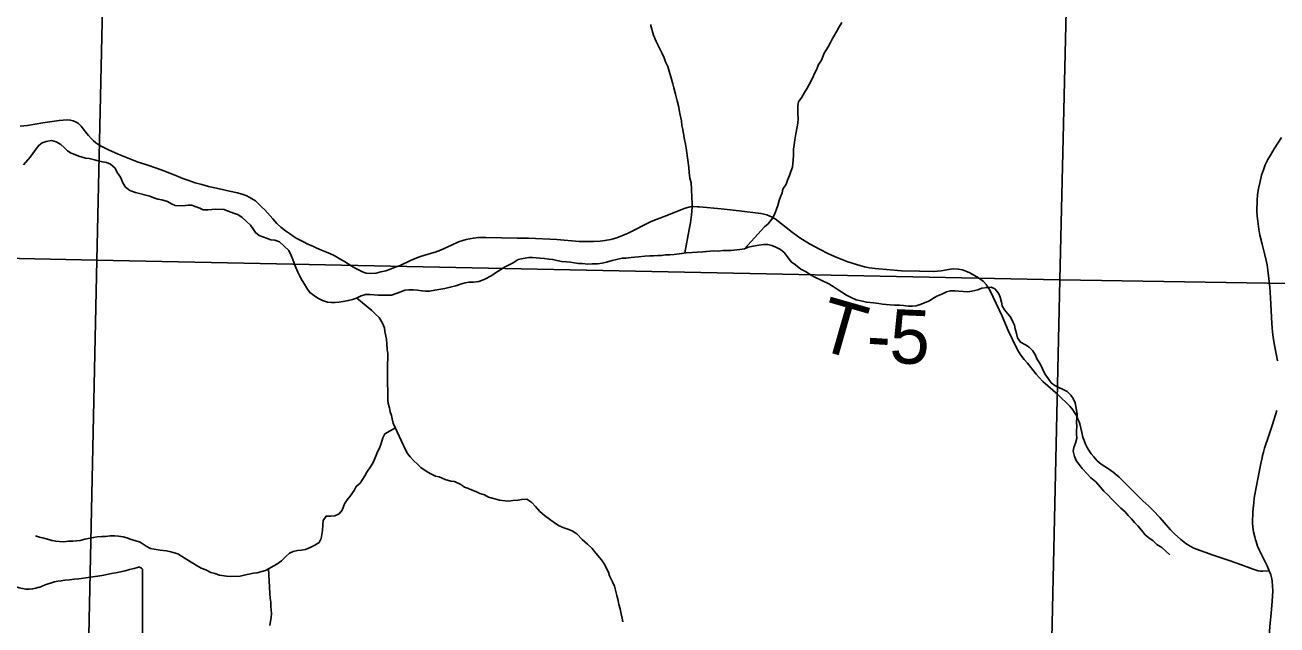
# Model space of a CAD drawing. Extents: x 0 to 34, y 0 to 22.
# Drawn here: x 27.832 to 29.148, y 19.195 to 19.826 of the extents above; entities that cross this region are included whole.
import ezdxf

# ---------------------------------------------------------------- set-up
doc = ezdxf.new("R2010")
doc.units = 0
for name, color, linetype in [('GM_X_Corporation', 7, 'Continuous'), ('GM_X_County_Road', 7, 'Continuous'), ('GM_X_Minor_River', 7, 'Continuous'), ('GM_X_State_Shield', 7, 'Continuous'), ('GM_X_Township_Road', 7, 'Continuous'), ('GM_X_Township_Road_Text', 7, 'Continuous')]:
    doc.layers.add(name, color=color, linetype=linetype)

msp = doc.modelspace()

# ---------------------------------------------------------------- linework, layer by layer
at = {"layer": 'GM_X_Corporation'}
for points in [[(28.9396, 20.3907), (28.9198, 19.5578), (27.9077, 19.5783), (27.9263, 20.4078)], [(29.9657, 20.3723), (29.946, 19.5413), (28.9198, 19.5578), (28.9396, 20.3907)], [(27.9077, 19.5783), (27.8861, 18.5601), (27.0567, 18.5863), (27.0782, 19.5962)], [(27.9077, 19.5783), (28.9198, 19.5578), (28.8973, 18.5532), (27.8861, 18.5601)], [(28.9198, 19.5578), (29.946, 19.5413), (29.9261, 18.5329), (28.8973, 18.5532)]]:
    msp.add_lwpolyline(points, close=True, dxfattribs=at)
at = {"layer": 'GM_X_County_Road'}
for points in [[(29.1486, 19.4725), (29.1455, 19.4893), (29.1441, 19.4973), (29.1434, 19.5031), (29.1429, 19.5074), (29.1425, 19.512), (29.1411, 19.5387), (29.1404, 19.55), (29.1395, 19.5593), (29.1384, 19.5681), (29.1376, 19.5737), (29.1367, 19.5781), (29.1354, 19.5839), (29.1325, 19.5952), (29.13, 19.6046), (29.1288, 19.6112), (29.1278, 19.6194), (29.1273, 19.6247), (29.127, 19.6298), (29.1271, 19.6414), (29.1277, 19.647), (29.1286, 19.6537), (29.1302, 19.6611), (29.1319, 19.6679), (29.1338, 19.6735), (29.1357, 19.6785), (29.1384, 19.6842), (29.1411, 19.6889), (29.1451, 19.6954), (29.1529, 19.7074)], [(29.1391, 19.1751), (29.1408, 19.1975), (29.1418, 19.2073), (29.143, 19.2202), (29.1437, 19.2305), (29.1435, 19.2363), (29.143, 19.2412), (29.1427, 19.2435), (29.1415, 19.2478), (29.1399, 19.2519), (29.1376, 19.2572), (29.136, 19.2606), (29.1297, 19.2733), (29.1277, 19.2779), (29.126, 19.2828), (29.1256, 19.2845), (29.1247, 19.2876), (29.1235, 19.2928), (29.1228, 19.2979), (29.1224, 19.3024), (29.1226, 19.3137), (29.1229, 19.3174), (29.1236, 19.3235), (29.1242, 19.3283), (29.1259, 19.3377), (29.131, 19.3649), (29.1323, 19.3709), (29.1328, 19.3732), (29.1337, 19.3767), (29.1349, 19.381), (29.1397, 19.3953), (29.1433, 19.4059), (29.148, 19.4205)]]:
    msp.add_lwpolyline(points, dxfattribs=at)
at = {"layer": 'GM_X_Minor_River'}
for points in [[(28.6909, 19.8282), (28.688, 19.8236), (28.6854, 19.819), (28.681, 19.8113), (28.6788, 19.8071), (28.6763, 19.8025), (28.6722, 19.796), (28.6693, 19.7887), (28.666, 19.7834), (28.6646, 19.7792), (28.662, 19.7746), (28.6602, 19.7703), (28.6565, 19.7631), (28.6543, 19.7592), (28.6514, 19.7546), (28.6488, 19.7497), (28.6451, 19.745), (28.6444, 19.7409), (28.6446, 19.7318), (28.6447, 19.7272), (28.6444, 19.7223), (28.6437, 19.7185), (28.6423, 19.7112), (28.6413, 19.7048), (28.6406, 19.6998), (28.6399, 19.6952), (28.6401, 19.688), (28.6394, 19.6801), (28.6388, 19.6763), (28.6373, 19.6717), (28.6359, 19.6675), (28.6337, 19.6625), (28.6323, 19.6583), (28.6289, 19.6529), (28.6279, 19.6491), (28.6264, 19.6449), (28.625, 19.6411), (28.6236, 19.6358), (28.6221, 19.6319), (28.62, 19.6266), (28.617, 19.6216), (28.6133, 19.6166), (28.6096, 19.6135), (28.5884, 19.5904)], [(28.4897, 19.8261), (28.4929, 19.8148), (28.4957, 19.8084), (28.4972, 19.8047), (28.5019, 19.7956), (28.5039, 19.7911), (28.5055, 19.787), (28.5078, 19.7821), (28.5091, 19.7772), (28.5111, 19.7711), (28.5131, 19.7636), (28.5143, 19.7594), (28.5159, 19.753), (28.5176, 19.7458), (28.5192, 19.7405), (28.5205, 19.7326), (28.5221, 19.7247), (28.5226, 19.7201), (28.5238, 19.7156), (28.5247, 19.7091), (28.5255, 19.7054), (28.5263, 19.7004), (28.5271, 19.6963), (28.5289, 19.6834), (28.5298, 19.6758), (28.5303, 19.6705), (28.5311, 19.6645), (28.5323, 19.6596), (28.5328, 19.6531), (28.533, 19.644), (28.5335, 19.6387), (28.5335, 19.6346), (28.5332, 19.63), (28.5329, 19.6262), (28.5316, 19.6178), (28.5302, 19.6106), (28.5258, 19.586)], [(27.8308, 19.6787), (27.8379, 19.6868), (27.8404, 19.6906), (27.8441, 19.6953), (27.8467, 19.6991), (27.8505, 19.7018), (27.8546, 19.703), (27.8603, 19.7043), (27.8652, 19.7028), (27.8698, 19.6999), (27.8736, 19.6969), (27.8771, 19.6932), (27.8809, 19.691), (27.8847, 19.6895), (27.8889, 19.6877), (27.8958, 19.6855), (27.8999, 19.6852), (27.9053, 19.6838), (27.9091, 19.6827), (27.9136, 19.6817), (27.9178, 19.681), (27.922, 19.6792), (27.927, 19.6751), (27.9293, 19.6706), (27.9325, 19.6657), (27.9356, 19.6589), (27.9379, 19.6552), (27.9425, 19.6515), (27.9486, 19.6497), (27.9635, 19.6458), (27.9677, 19.6439), (27.9718, 19.6425), (27.976, 19.6418), (27.9821, 19.64), (27.9863, 19.6378), (27.9901, 19.636), (27.9981, 19.6354), (28.0037, 19.6362), (28.0075, 19.6363), (28.0113, 19.6348), (28.0159, 19.633), (28.0197, 19.6312), (28.0243, 19.6313), (28.0329, 19.6322), (28.0417, 19.6316), (28.0474, 19.6294), (28.0523, 19.6276), (28.0561, 19.6265), (28.0607, 19.6232), (28.0646, 19.6195)], [(28.0646, 19.6195), (28.0692, 19.6154), (28.0719, 19.6116), (28.0746, 19.6075), (28.0785, 19.6045), (28.0861, 19.6016), (28.0907, 19.5998), (28.0948, 19.5995), (28.0998, 19.5977), (28.1048, 19.5932), (28.1094, 19.5887), (28.1121, 19.5835), (28.1137, 19.579), (28.1153, 19.5752), (28.1169, 19.5707), (28.1189, 19.5658), (28.1212, 19.5616), (28.1236, 19.5571), (28.1259, 19.5534), (28.1286, 19.5492), (28.1318, 19.5444), (28.1364, 19.541), (28.1402, 19.5384), (28.1451, 19.5359), (28.1501, 19.5344), (28.1539, 19.5338), (28.1584, 19.5338), (28.1622, 19.5343), (28.1667, 19.5351), (28.172, 19.536), (28.1765, 19.5372), (28.1807, 19.5384), (28.1855, 19.5411), (28.1901, 19.5424), (28.1946, 19.5424), (28.2033, 19.5418), (28.2086, 19.5415), (28.2173, 19.5417), (28.2222, 19.5433), (28.2271, 19.5453), (28.2316, 19.5469), (28.2358, 19.5473), (28.2403, 19.5474), (28.2448, 19.5471), (28.2494, 19.5464), (28.2532, 19.5457), (28.2574, 19.5458), (28.263, 19.5471), (28.2672, 19.5475), (28.2736, 19.5488), (28.2792, 19.55), (28.2849, 19.5516), (28.2901, 19.5532), (28.295, 19.5545), (28.2988, 19.5553), (28.3037, 19.5554), (28.3094, 19.5562), (28.3147, 19.5582), (28.3229, 19.5625), (28.3278, 19.5657), (28.3319, 19.5684), (28.3356, 19.5707), (28.3398, 19.5727), (28.3454, 19.5758), (28.3506, 19.579), (28.3559, 19.5802), (28.3619, 19.5814), (28.3657, 19.5811), (28.3733, 19.5805), (28.3782, 19.5802), (28.3828, 19.5795), (28.3869, 19.5792), (28.3911, 19.5782), (28.3961, 19.5771), (28.4014, 19.5768), (28.4055, 19.5765), (28.4093, 19.5758), (28.4143, 19.5748), (28.418, 19.5748), (28.4237, 19.5742), (28.4283, 19.5746), (28.4339, 19.5747), (28.4388, 19.5752), (28.4434, 19.5764), (28.4494, 19.5781), (28.4599, 19.5805), (28.4637, 19.5806), (28.4694, 19.5811), (28.4769, 19.582), (28.4838, 19.5825), (28.489, 19.5829), (28.4928, 19.583), (28.4974, 19.5835), (28.5011, 19.5835), (28.5053, 19.584), (28.5098, 19.5841), (28.5147, 19.5845), (28.5223, 19.5854), (28.5272, 19.5863), (28.5336, 19.5864), (28.5446, 19.5873)], [(28.5446, 19.5873), (28.5563, 19.5883), (28.5612, 19.588), (28.5658, 19.5885), (28.5741, 19.5886), (28.5835, 19.5895), (28.5884, 19.5904), (28.5922, 19.592), (28.5975, 19.5932), (28.6035, 19.5941), (28.6084, 19.5949), (28.6129, 19.595), (28.6171, 19.5939), (28.6213, 19.5921), (28.6263, 19.5895), (28.6301, 19.5866), (28.6336, 19.5821), (28.6375, 19.5768), (28.6421, 19.5735), (28.6475, 19.569), (28.6524, 19.5665), (28.6585, 19.5628), (28.6624, 19.5606), (28.6769, 19.5536), (28.6815, 19.5507), (28.686, 19.5481), (28.6906, 19.5448), (28.6956, 19.5418), (28.7006, 19.5392), (28.7059, 19.5367), (28.7124, 19.5353), (28.7166, 19.5342), (28.7241, 19.5336), (28.7295, 19.5329), (28.7336, 19.5322), (28.7374, 19.5319), (28.7416, 19.5316), (28.7461, 19.5313), (28.7514, 19.531), (28.7556, 19.5307), (28.7605, 19.5301), (28.7651, 19.5301), (28.7689, 19.5306), (28.7741, 19.5322), (28.7783, 19.5338), (28.7828, 19.5358), (28.7865, 19.5381), (28.7906, 19.5405), (28.7959, 19.5428), (28.8008, 19.5452), (28.8049, 19.5464), (28.8098, 19.5461), (28.8136, 19.5458), (28.8231, 19.5452), (28.8272, 19.5457), (28.8336, 19.5473), (28.8378, 19.5489), (28.8438, 19.5497), (28.8476, 19.5502), (28.8514, 19.5484), (28.8553, 19.5439), (28.8572, 19.5394), (28.8585, 19.5344), (28.8593, 19.5303), (28.8616, 19.5262), (28.8651, 19.522), (28.8682, 19.5183), (28.8706, 19.5138), (28.8721, 19.51), (28.873, 19.5062), (28.8742, 19.5013), (28.8754, 19.4968), (28.8785, 19.4923), (28.8839, 19.4894), (28.8877, 19.4872), (28.8915, 19.4831), (28.8943, 19.4785), (28.8958, 19.4748), (28.899, 19.4695), (28.9017, 19.4643), (28.9041, 19.459), (28.9076, 19.4541), (28.9107, 19.4496), (28.9145, 19.4467), (28.9187, 19.4448), (28.9225, 19.443), (28.9275, 19.4404), (28.9313, 19.4367), (28.934, 19.433), (28.936, 19.4284), (28.9368, 19.4247), (28.9373, 19.4209), (28.9381, 19.4163), (28.9378, 19.4125), (28.9375, 19.4084), (28.9376, 19.4034), (28.9373, 19.3996), (28.9373, 19.3958), (28.9378, 19.3913), (28.9364, 19.386), (28.9346, 19.3817)], [(28.181, 19.5386), (28.1968, 19.5254), (28.2006, 19.5217), (28.2045, 19.5183), (28.208, 19.5123), (28.21, 19.5074), (28.2104, 19.5036), (28.2121, 19.4953), (28.2125, 19.4904), (28.213, 19.4847), (28.2135, 19.4805), (28.2136, 19.4752), (28.2133, 19.4692), (28.2134, 19.4635), (28.2131, 19.4581), (28.2136, 19.4316), (28.214, 19.4278), (28.2153, 19.4233), (28.2161, 19.4191), (28.2173, 19.4153), (28.2181, 19.4116), (28.2193, 19.407), (28.2323, 19.3792), (28.2343, 19.3754), (28.237, 19.3717), (28.2408, 19.3676), (28.2447, 19.3642), (28.2482, 19.3605), (28.255, 19.356), (28.2596, 19.3535), (28.2638, 19.3516), (28.2676, 19.3506), (28.2737, 19.348), (28.2798, 19.3462), (28.2836, 19.3459), (28.2905, 19.3426), (28.2943, 19.34), (28.2985, 19.3386), (28.3023, 19.3368), (28.3061, 19.3353), (28.3103, 19.3331), (28.3153, 19.3317), (28.3195, 19.3295), (28.3259, 19.3277), (28.3309, 19.3263), (28.3369, 19.3256), (28.3407, 19.3253), (28.3449, 19.3258), (28.3502, 19.3262), (28.3543, 19.3271), (28.3596, 19.3272), (28.365, 19.3238), (28.3688, 19.3197), (28.3735, 19.3145), (28.3781, 19.31), (28.3834, 19.3063), (28.3873, 19.3034), (28.393, 19.2997), (28.3987, 19.2971), (28.4029, 19.2957), (28.4075, 19.2939), (28.4121, 19.2909), (28.4179, 19.2849), (28.4236, 19.2801), (28.4283, 19.2756), (28.4321, 19.2704), (28.4383, 19.2637), (28.4418, 19.2584), (28.4434, 19.2546), (28.4454, 19.2505), (28.4466, 19.2467), (28.4497, 19.2403), (28.4517, 19.2358), (28.4529, 19.2317), (28.4541, 19.226), (28.4557, 19.2207), (28.4565, 19.2166), (28.4578, 19.212), (28.459, 19.2067), (28.4598, 19.2022), (28.4607, 19.1984)], [(28.2215, 19.4024), (28.2104, 19.3959), (28.2082, 19.3916), (28.2065, 19.3859), (28.205, 19.381), (28.2028, 19.3771), (28.201, 19.3725), (28.1981, 19.366), (28.1955, 19.3611), (28.1915, 19.3557), (28.1893, 19.3518), (28.1845, 19.3442), (28.1804, 19.3407), (28.1782, 19.3365), (28.1741, 19.3303), (28.1708, 19.3265), (28.1682, 19.3223), (28.1657, 19.3158), (28.1624, 19.3119), (28.1579, 19.3099), (28.1537, 19.3095), (28.1488, 19.3094), (28.1455, 19.3048), (28.1452, 19.3006), (28.1449, 19.2945), (28.1442, 19.29), (28.1435, 19.2858), (28.1413, 19.2819), (28.1368, 19.2788), (28.132, 19.2765), (28.1271, 19.2745), (28.1225, 19.2736), (28.1188, 19.2732), (28.1142, 19.2723), (28.1101, 19.2704), (28.1064, 19.2669), (28.1019, 19.2626), (28.0971, 19.2591), (28.0851, 19.2525), (28.0813, 19.2513), (28.0764, 19.25), (28.0726, 19.2496), (28.0674, 19.2484), (28.0625, 19.2475), (28.0583, 19.2463), (28.0485, 19.2461), (28.0439, 19.2464), (28.0367, 19.2474), (28.0318, 19.2493), (28.0276, 19.2503), (28.0223, 19.2529), (28.0173, 19.2547), (28.0116, 19.2584), (27.9997, 19.2658), (27.9928, 19.2698), (27.9856, 19.272), (27.981, 19.273), (27.9742, 19.2737), (27.9681, 19.2747), (27.9643, 19.2754), (27.9598, 19.278), (27.9533, 19.282), (27.9479, 19.2838), (27.9437, 19.2849), (27.9392, 19.2867), (27.9354, 19.2878), (27.9304, 19.2885), (27.9266, 19.2888), (27.9217, 19.2887), (27.9168, 19.2882), (27.913, 19.2881), (27.9081, 19.2877), (27.9044, 19.2869), (27.8953, 19.2852), (27.8904, 19.2839), (27.8825, 19.2831), (27.8779, 19.283), (27.873, 19.2825), (27.8685, 19.2828), (27.8647, 19.2831), (27.8609, 19.2838), (27.8521, 19.2863), (27.8476, 19.2874), (27.8434, 19.2888)], [(28.9346, 19.3817), (28.9339, 19.3779), (28.9351, 19.3723), (28.9375, 19.3674), (28.9402, 19.3636), (28.9433, 19.3595), (28.9487, 19.3539), (28.9525, 19.3498), (28.9575, 19.3454), (28.9622, 19.3401), (28.966, 19.3356), (28.9706, 19.3315), (28.9741, 19.3278), (28.9787, 19.323), (28.9841, 19.3177), (28.9884, 19.314), (28.9915, 19.3103), (28.9953, 19.3066), (28.9984, 19.3028), (29.0019, 19.2991), (29.0057, 19.2946), (29.0096, 19.2897), (29.0134, 19.2868), (29.018, 19.2834), (29.0219, 19.2797), (29.0269, 19.2764), (29.0353, 19.2689)], [(28.0883, 19.2543), (28.0897, 19.2283), (28.0901, 19.2233), (28.0906, 19.2192), (28.0907, 19.215), (28.0911, 19.2108), (28.0912, 19.207), (28.0909, 19.2029), (28.0902, 19.1991), (28.0895, 19.1945)]]:
    msp.add_lwpolyline(points, dxfattribs=at)
at = {"layer": 'GM_X_State_Shield'}
msp.add_line((27.9559, 19.1477), (27.9559, 19.2524), dxfattribs=at)
for centre, major_axis, start_param, end_param in [((27.8385, 19.5203), (0.3495, 0), 4.814394, 5.042369), ((27.9522, 19.2528), (0.00367, 0), 6.141152, 7.989035), ((27.8358, 19.2541), (0.0267, 0), 4.081561, 5.145723), ((27.883, 19.1863), (0.0703, 0), 1.699011, 2.107814)]:
    msp.add_ellipse(centre, major_axis=major_axis, ratio=0.8, start_param=start_param, end_param=end_param, dxfattribs=at)
at = {"layer": 'GM_X_Township_Road'}
for points in [[(27.8273, 19.7191), (27.8349, 19.7201), (27.8512, 19.7229), (27.8681, 19.7251), (27.8724, 19.7256), (27.8772, 19.7258), (27.8798, 19.7256), (27.883, 19.7247), (27.8861, 19.7234), (27.8887, 19.7219), (27.8915, 19.7194), (27.8935, 19.7166), (27.8973, 19.7114), (27.899, 19.7094), (27.9017, 19.7063), (27.904, 19.7042), (27.9069, 19.7018), (27.91, 19.6997), (27.9139, 19.6975), (27.9201, 19.6945), (27.9302, 19.6899), (27.9426, 19.6848), (27.9513, 19.6815), (27.9592, 19.679), (27.9717, 19.6747), (27.9783, 19.6723), (27.9861, 19.6693), (27.9934, 19.6664), (27.9981, 19.6644), (28.0034, 19.6624), (28.0112, 19.6598), (28.0181, 19.6578), (28.0253, 19.656), (28.0366, 19.6533), (28.0471, 19.6511), (28.0556, 19.6491), (28.0616, 19.6474), (28.0656, 19.6459), (28.0703, 19.6434), (28.0744, 19.6408), (28.0776, 19.6378), (28.0808, 19.6346), (28.0843, 19.6312), (28.0926, 19.6219), (28.0971, 19.617), (28.1011, 19.6132), (28.1061, 19.6093), (28.1101, 19.6064), (28.1141, 19.6035), (28.1174, 19.6016), (28.1237, 19.5984), (28.1301, 19.595), (28.1347, 19.593), (28.1389, 19.5912), (28.144, 19.5891), (28.1493, 19.587), (28.1535, 19.5852), (28.1571, 19.5834), (28.1607, 19.5814), (28.1643, 19.5793), (28.1681, 19.5769), (28.1718, 19.5745), (28.1758, 19.5722), (28.1799, 19.5698), (28.1835, 19.568), (28.1871, 19.5662), (28.191, 19.5649), (28.1949, 19.5643), (28.2012, 19.5649), (28.2064, 19.5661), (28.2116, 19.5674), (28.2153, 19.5686), (28.2189, 19.57), (28.2224, 19.5713), (28.2266, 19.573), (28.2376, 19.5782), (28.2423, 19.5802), (28.247, 19.582), (28.257, 19.585), (28.2633, 19.5868), (28.2691, 19.589), (28.2804, 19.5943), (28.288, 19.5976), (28.2925, 19.5991), (28.2959, 19.6001), (28.2997, 19.6009), (28.3036, 19.6016), (28.3088, 19.6021), (28.3167, 19.6022), (28.3495, 19.6017), (28.3616, 19.6015), (28.3912, 19.6), (28.4146, 19.5982), (28.4236, 19.5979), (28.4296, 19.598), (28.4369, 19.5985), (28.4417, 19.5991), (28.448, 19.6002), (28.4503, 19.6007), (28.4542, 19.602), (28.4619, 19.605), (28.4662, 19.607), (28.4897, 19.6187), (28.492, 19.6198), (28.5039, 19.6245), (28.5227, 19.6318), (28.5262, 19.6331), (28.5312, 19.6344), (28.5349, 19.6348), (28.5391, 19.6346)], [(28.5391, 19.6346), (28.5411, 19.6345), (28.5638, 19.6323), (28.583, 19.6304), (28.6057, 19.6276), (28.6089, 19.6269), (28.6118, 19.6261), (28.6149, 19.6248), (28.6168, 19.6239), (28.6185, 19.623), (28.6205, 19.6218), (28.6389, 19.6075), (28.6465, 19.602), (28.6569, 19.5956), (28.6679, 19.5895), (28.6761, 19.5855), (28.683, 19.5824), (28.6901, 19.5795), (28.6972, 19.5767), (28.7097, 19.5728), (28.7147, 19.5716), (28.7198, 19.5705), (28.7259, 19.5696), (28.7297, 19.5692), (28.7457, 19.5679), (28.7536, 19.5674), (28.7724, 19.5668), (28.7874, 19.5664), (28.7953, 19.5673), (28.805, 19.5689), (28.8084, 19.5693), (28.813, 19.5691), (28.8175, 19.5682), (28.821, 19.5669), (28.8253, 19.5651), (28.8345, 19.56), (28.8369, 19.5583), (28.8395, 19.5561), (28.8423, 19.5529), (28.8436, 19.5512), (28.8453, 19.5486), (28.8466, 19.5462), (28.8593, 19.5195), (28.8657, 19.5045), (28.8696, 19.4958), (28.8731, 19.4885), (28.8764, 19.4824), (28.8788, 19.4785), (28.8825, 19.4739), (28.8857, 19.4702), (28.8951, 19.4585), (28.8981, 19.455), (28.9021, 19.4508), (28.9177, 19.4373), (28.9303, 19.4252), (28.9335, 19.4211), (28.9354, 19.4182), (28.9372, 19.4151), (28.9392, 19.4108), (28.94, 19.4086), (28.9407, 19.4064), (28.9428, 19.3972), (28.944, 19.3926), (28.9453, 19.3888), (28.9468, 19.3852), (28.9487, 19.3816), (28.9515, 19.3771), (28.9529, 19.3749), (28.9554, 19.3717), (28.9591, 19.3676), (28.9634, 19.364), (28.971, 19.359), (28.976, 19.3555), (28.9821, 19.3503), (28.9894, 19.3432), (28.9976, 19.3349), (29.0039, 19.3286), (29.0071, 19.3256)], [(29.0071, 19.3256), (29.0133, 19.3199), (29.0179, 19.3154), (29.0248, 19.308), (29.0363, 19.2951), (29.0405, 19.2907), (29.0469, 19.285), (29.0524, 19.2808), (29.0567, 19.278), (29.0607, 19.2759), (29.0634, 19.2747), (29.0809, 19.2685), (29.0968, 19.2633), (29.106, 19.2601), (29.1191, 19.255), (29.1239, 19.2534), (29.1284, 19.2521), (29.1303, 19.2518), (29.1333, 19.2516), (29.1399, 19.2519)]]:
    msp.add_lwpolyline(points, dxfattribs=at)

# ---------------------------------------------------------------- texts
at = {"layer": 'GM_X_Township_Road_Text'}
for s, rotation, p in [('T', 344.0364, (28.6618, 19.4859)), ('5', 357.5471, (28.7401, 19.4705)), ('-', 356.4484, (28.7156, 19.472))]:
    msp.add_text(s, height=0.0568, rotation=rotation, dxfattribs=at).set_placement(p)

doc.saveas('drawing.dxf')
